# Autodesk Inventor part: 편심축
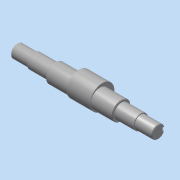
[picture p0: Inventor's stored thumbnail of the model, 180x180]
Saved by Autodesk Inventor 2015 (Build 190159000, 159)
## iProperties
Created: 2015-10
Part Number: 편심축
Document SubType Name: Modeling
Designer: mdu
Density: 7.86 g/cm^3
Material: 강철, 연강
Mass: 1327.93 g
Surface Area: 248.524 cm^2
Volume: 168.947 cm^3
Appearance: 강철
Author: mdu
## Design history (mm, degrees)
sketch "스케치1"
  geometry: L1 (-20.5, -41.331)-(-20.5, 32.669) reference; L2 (7.5, -30.031)-(7.5, 21.369) reference; L3 (135.5, -30.331)-(135.5, 21.669) reference; L4 (121.5, 21.369)-(121.5, -30.031) reference; L5 (184.5, -4.331)-(-57.5, -4.331); L6 (184.5, -4.331)-(184.5, 6.669); L7 (154.5, 8.169)-(121.5, 8.169); L8 (121.5, 8.169)-(121.5, 11.669); L9 (121.5, 11.669)-(7.5, 11.669); L10 (7.5, 11.669)-(7.5, 8.169); L11 (7.5, 8.169)-(-27.5, 8.169); L12 (-27.5, 8.169)-(-27.5, 6.669); L13 (-27.5, 6.669)-(-57.5, 6.669); L14 (-57.5, 6.669)-(-57.5, -4.331); L15 (154.5, 8.169)-(154.5, 6.669); L16 (154.5, 6.669)-(184.5, 6.669); C1 r 32.5 at (64.5, -4.331) reference; 1 further point
  constraints: 24 end point, 8 perpendicular, 5 point on line, 3 parallel, 2 collinear
  dimensions: "d1" = 25 diameter of L11 L5; "d2" = 32 diameter of L9 L5; "d3" = 22 diameter of L13 L5; "d4" = 35 distance of L10.end L11.end; "d5" = 30 distance of L12.end L13.end; "d15" = 33 distance of L7.start L7.end; "d26" = 30 distance of L15.end L6.end
revolve "회전1" sketch "스케치1" stored, may be unused: angle "d6" = 90 deg
node "작업 평면1"
sketch "스케치2"
  geometry: C1 r 16 at (0, 0) reference; C2 r 16 at (0, 0) reference; C3 r 20.75 at (0, 4); C4 r 16 at (0, 0) reference; 1 further point
  constraints: 1 centre point, 1 vertical alignment
  dimensions: "d8" = 41.5 diameter of C3; "d25" = 4 distance of C3.centre C1.centre
extrude "돌출1" join sketch "스케치2" stored distance "d9" = 40; taper "d10" = 0 deg
chamfer "모따기1" distance "d11" = 1; stored, may be unused: second distance "d12" = 2, angle "d13" = 45 deg
node "작업 평면2"
sketch "스케치3"
  geometry: L1 (-15, -10)-(-15, 10) reference; L2 (-15, 3)-(0, 3); L3 (0, -3)-(-15, -3); A1 r 3 centre (0, 0) between (0, -3) and (0, 3); 2 further points
  constraints: 4 end point, 2 perpendicular, 2 point on circle, 2 point on line, 2 tangent, 1 centre point, 1 horizontal alignment, 1 midpoint
  dimensions: "d16" = 18 dimension on A1 L1; "d17" = 6 distance between parallel lines of L3 L2
extrude "돌출2" cut sketch "스케치3" distance "d18" = 3.5; taper "d19" = 0 deg
node "작업 평면3"
sketch "스케치5"
  geometry: C1 r 20.75 at (0, 0) reference; 1 further point
feature "돌출 곡면1" sketch "스케치5" dims "d27" = 40, "d28" = 0
node "솔리드1"
mirror "대칭1"
node "참조1"
node "참조2"
node "참조3"
node "참조4"
node "참조5"
node "투영된 루프1"
node "곡면1"
